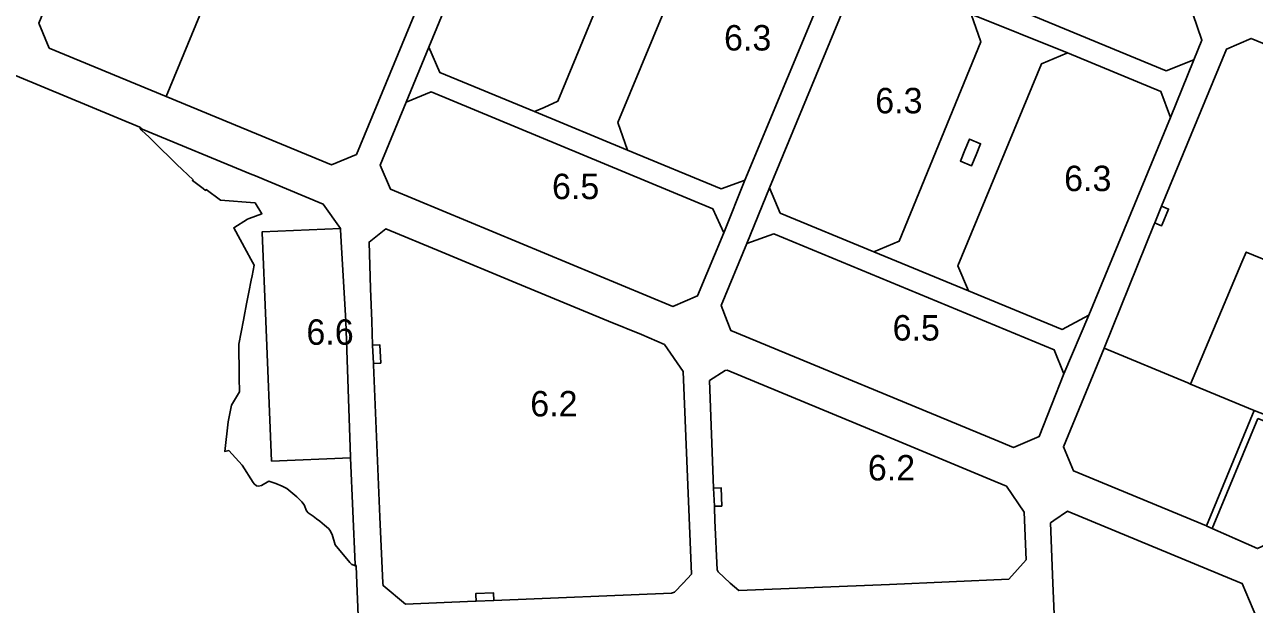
# Model space of a CAD drawing. Extents: x 598968 to 613553, y 4409678 to 4430833.
# Drawn here: x 605206 to 605786, y 4415736 to 4416009 of the extents above; entities that cross this region are included whole.
import ezdxf

# ---------------------------------------------------------------- set-up
doc = ezdxf.new("R2010")
doc.units = 0
for name, color, linetype in [('1', 7, 'Continuous'), ('Zona 6.2 - ANNEX III E', 7, 'Continuous'), ('Zona 6.3 - ANNEX III E', 7, 'Continuous'), ('Zona 6.5 - ANNEX III E', 7, 'Continuous'), ('Zona 6.6 - ANNEX III E', 7, 'Continuous')]:
    doc.layers.add(name, color=color, linetype=linetype)

msp = doc.modelspace()

# ---------------------------------------------------------------- linework, layer by layer
at = {"layer": '1'}
for points in [[(605413.2444, 4416069.7069), (605409.3441, 4416060.2821), (605400.3206, 4416038.4781), (605362.8413, 4415947.9137), (605351.0859, 4415943.0399), (605273.0979, 4415975.3137), (605273.0943, 4415975.3146), (605217.9054, 4415998.1523), (605213.031, 4416009.9096), (605290.8173, 4416197.8715), (605302.5757, 4416202.7458), (605357.7632, 4416179.9075), (605435.7532, 4416147.6329), (605440.6276, 4416135.8756)], [(605357.7632, 4416179.9075), (605302.5757, 4416202.7458), (605290.8173, 4416197.8715), (605213.031, 4416009.9096), (605217.9054, 4415998.1523), (605273.0943, 4415975.3146), (605314.0146, 4416074.194)], [(605378.8742, 4415931.583), (605374.0758, 4415942.9193), (605386.2096, 4415972.6661), (605397.0031, 4415998.6269), (605436.4772, 4416094.1213), (605447.8156, 4416121.3723), (605451.6756, 4416130.9923), (605463.8177, 4416135.792), (605596.0043, 4416080.9851), (605601.2443, 4416069.2054), (605596.8544, 4416058.5554), (605586.2696, 4416032.5788), (605546.0952, 4415935.8658), (605536.0554, 4415911.0159), (605523.7056, 4415881.2859), (605512.0544, 4415876.325)], [(605536.7596, 4416062.2366), (605492.3118, 4416080.6494), (605497.2153, 4416068.7337), (605457.836, 4415973.154), (605451.3144, 4415970.2236), (605447.6218, 4415968.5645), (605446.8861, 4415968.2339), (605490.6274, 4415950.0969), (605486.1528, 4415963.1027), (605525.295, 4416057.4442)], [(605400.3206, 4416038.4781), (605314.0146, 4416074.194), (605273.0943, 4415975.3146), (605273.0979, 4415975.3137), (605351.0859, 4415943.0399), (605362.8413, 4415947.9137)], [(605534.9055, 4415876.7261), (605546.9853, 4415906.0361), (605557.6473, 4415932.3467), (605597.0697, 4416027.6512), (605608.1698, 4416054.0843), (605612.4942, 4416064.0456), (605624.3651, 4416069.2253), (605757.3031, 4416014.3485), (605761.6531, 4416001.9487), (605757.7965, 4415992.5856), (605746.7334, 4415965.3688), (605708.314, 4415872.219), (605696.521, 4415844.501), (605684.9027, 4415814.9883), (605672.8055, 4415809.8995), (605664.0589, 4415813.5143), (605539.3425, 4415865.069), (605537.6712, 4415869.46)], [(605757.7965, 4415992.5856), (605744.8033, 4415987.4486), (605612.6443, 4416042.1758), (605608.1716, 4416054.0794), (605608.1698, 4416054.0843), (605597.0697, 4416027.6512), (605597.0744, 4416027.6532), (605609.4195, 4416032.6605), (605652.8502, 4416014.2157), (605698.1847, 4415995.9269), (605742.2155, 4415977.7057), (605746.7334, 4415965.3688)], [(605698.1847, 4415995.9269), (605652.8502, 4416014.2157), (605657.4041, 4416001.087), (605618.8546, 4415907.1673), (605606.8917, 4415902.1501), (605651.6001, 4415883.711), (605646.5345, 4415895.4679), (605685.8939, 4415990.6876), (605697.9061, 4415995.8082)], [(605446.8861, 4415968.2339), (605402.1451, 4415986.7234), (605397.0051, 4415998.6223), (605397.0031, 4415998.6269), (605386.2096, 4415972.6661), (605386.2143, 4415972.6681), (605398.1014, 4415977.5484), (605530.9554, 4415922.4057), (605536.0554, 4415911.0159), (605546.0952, 4415935.8658), (605545.711, 4415935.7281), (605543.9899, 4415935.1113), (605534.7923, 4415931.8151), (605490.6274, 4415950.0969)], [(605355.2362, 4415913.0768), (605347.158, 4415924.6423), (605314.4337, 4415938.1846), (605313.5395, 4415938.5546), (605261.6924, 4415960.0105), (605260.571, 4415960.9504), (605260.8798, 4415960.2221), (605261.2803, 4415959.6602), (605261.4944, 4415959.4646), (605265.0439, 4415956.1683), (605270.2901, 4415950.9933), (605275.0034, 4415946.3695), (605278.1279, 4415943.3045), (605285.7383, 4415936.1067), (605285.4254, 4415935.6848), (605290.4452, 4415931.9598), (605291.649, 4415931.0665), (605291.9468, 4415931.468), (605298.7404, 4415926.4624), (605314.9486, 4415925.2416), (605315.0085, 4415925.1467), (605318.2121, 4415920.0693), (605312.2428, 4415917.8544), (605311.429, 4415917.5525), (605304.9522, 4415913.4434), (605310.9899, 4415902.3558), (605313.0084, 4415898.6491), (605314.5475, 4415895.8227), (605313.5678, 4415890.7229), (605313.179, 4415888.699), (605312.0939, 4415883.0503), (605311.0275, 4415877.4992), (605309.8928, 4415871.5921), (605309.5598, 4415869.8591), (605307.3981, 4415858.6062), (605307.5178, 4415843.9522), (605307.5283, 4415842.6685), (605307.5823, 4415836.0602), (605303.854, 4415829.7247), (605302.3156, 4415821.905), (605300.7241, 4415807.9462), (605302.606, 4415808.3712), (605308.9648, 4415801.4807), (605314.0628, 4415793.2544), (605314.5213, 4415792.6602), (605315.7094, 4415791.7952), (605316.5529, 4415791.6266), (605317.9801, 4415791.9649), (605321.5554, 4415793.8687), (605324.7458, 4415792.9068), (605327.8196, 4415791.6484), (605329.9221, 4415790.4211), (605334.7373, 4415786.6255), (605337.1218, 4415784.1882), (605338.1042, 4415782.7254), (605339.3083, 4415779.9415), (605340.0639, 4415779.0656), (605342.3322, 4415777.3793), (605343.9217, 4415776.2449), (605345.5112, 4415775.1105), (605347.8213, 4415773.1917), (605348.6938, 4415772.4206), (605348.7072, 4415772.4087), (605349.6067, 4415771.6138), (605350.2642, 4415770.8176), (605351.34, 4415768.8282), (605352.7649, 4415763.9003), (605359.7785, 4415755.5556), (605359.8969, 4415755.4147), (605359.9141, 4415755.3942), (605360.4522, 4415754.754), (605360.4565, 4415754.7489), (605360.4907, 4415754.7082), (605360.8132, 4415754.5927), (605362.7145, 4415753.9115), (605362.1456, 4415754.7146), (605360.0838, 4415804.9775), (605322.8089, 4415803.448), (605322.805, 4415803.4479), (605320.0972, 4415869.4564), (605318.3859, 4415911.1749), (605318.37, 4415911.5642), (605318.3739, 4415911.5643)], [(605655.0833, 4415947.8739), (605652.9419, 4415942.6995), (605647.6752, 4415944.8791), (605649.8165, 4415950.0535), (605651.9579, 4415955.2279), (605657.2246, 4415953.0483)], [(605655.0833, 4415947.8739), (605657.2246, 4415953.0483), (605651.9579, 4415955.2279), (605649.8165, 4415950.0535), (605647.6752, 4415944.8791), (605652.9419, 4415942.6995)], [(605606.8917, 4415902.1501), (605562.7641, 4415920.3493), (605557.6494, 4415932.342), (605557.6473, 4415932.3467), (605546.9853, 4415906.0361), (605546.9899, 4415906.0378), (605559.7152, 4415910.6163), (605691.9542, 4415855.9389), (605696.521, 4415844.501), (605708.314, 4415872.219), (605695.7342, 4415865.5089), (605651.6001, 4415883.711)], [(605739.3519, 4415915.7293), (605739.3553, 4415915.7279), (605740.3602, 4415915.3083), (605742.5497, 4415914.3943), (605742.6336, 4415914.3593), (605742.8734, 4415914.9313), (605745.9335, 4415922.2293), (605742.6169, 4415923.6477), (605742.6135, 4415923.6492)], [(605512.7901, 4415741.5371), (605511.4201, 4415741.1471), (605511.4162, 4415741.147), (605427.5976, 4415737.6757), (605427.5937, 4415737.6756), (605419.2293, 4415737.3848), (605419.2254, 4415737.3846), (605418.8621, 4415737.3695), (605418.8582, 4415737.3693), (605385.8912, 4415735.9952), (605385.8874, 4415735.9951), (605375.3575, 4415744.7248), (605375.3033, 4415745.9135), (605373.8831, 4415777.0759), (605370.861, 4415848.8777), (605370.8372, 4415849.4437), (605370.4372, 4415858.0536), (605370.0115, 4415869.4573), (605369.4408, 4415884.7444), (605368.747, 4415906.7132), (605376.6082, 4415912.9627), (605403.2675, 4415901.8882), (605438.0464, 4415887.4644), (605481.6608, 4415869.4591), (605497.2059, 4415863.0416), (605508.1058, 4415858.4359), (605516.8658, 4415845.7061), (605519.1241, 4415792.0699), (605520.8761, 4415750.1371), (605516.9052, 4415745.9159), (605516.9092, 4415745.9159)], [(605869.8234, 4415865.9385), (605868.8373, 4415866.3466), (605861.4561, 4415869.4012), (605859.6588, 4415865.0584), (605854.0224, 4415867.3909), (605855.8197, 4415871.7337), (605811.673, 4415890.003), (605782.5432, 4415901.9801), (605780.5183, 4415897.185), (605756.2662, 4415839.756), (605786.3011, 4415827.3268), (605819.1595, 4415814.5422), (605820.1695, 4415816.4572), (605824.1395, 4415814.4072), (605828.9013, 4415823.0512), (605834.283, 4415831.3233), (605840.256, 4415839.1794), (605846.7878, 4415846.5772), (605853.8437, 4415853.4769), (605861.3857, 4415859.8417), (605869.3734, 4415865.6373)], [(605370.8372, 4415849.4437), (605370.8411, 4415849.4439), (605373.8877, 4415849.5953), (605374.2571, 4415849.6137), (605373.8671, 4415858.1636), (605370.4411, 4415858.0537), (605370.4372, 4415858.0536)], [(605756.2662, 4415839.756), (605756.2637, 4415839.7502), (605754.9408, 4415840.3044), (605715.5019, 4415856.6255), (605715.4985, 4415856.6269), (605696.2671, 4415810.1565), (605700.9829, 4415798.7817), (605763.7403, 4415772.8115), (605786.3011, 4415827.3268)], [(605611.3067, 4415815.8497), (605664.0589, 4415793.8101), (605669.3747, 4415791.5892), (605677.8546, 4415779.3595), (605678.7147, 4415756.7797), (605670.4848, 4415747.6996), (605614.2069, 4415745.2727), (605614.2029, 4415745.2725), (605543.1798, 4415742.3277), (605543.1759, 4415742.3276), (605539.1829, 4415745.9162), (605533.3959, 4415751.1173), (605532.9359, 4415752.1873), (605531.9457, 4415775.3474), (605531.6804, 4415781.5541), (605531.6559, 4415782.127), (605531.2958, 4415790.6369), (605529.3757, 4415841.3564), (605536.8156, 4415846.1364), (605537.7461, 4415846.2163)], [(605531.6559, 4415782.127), (605531.6598, 4415782.1271), (605534.84, 4415782.2257), (605535.1398, 4415782.2351), (605534.8758, 4415790.757), (605531.2998, 4415790.6371), (605531.2958, 4415790.6369)], [(605427.5937, 4415737.6756), (605427.4466, 4415741.2935), (605419.0808, 4415740.9457), (605419.1039, 4415740.3762), (605419.2254, 4415737.3846), (605419.2293, 4415737.3848)]]:
    msp.add_lwpolyline(points, close=True, dxfattribs=at)
for points in [[(605787.7946, 4415762.1719), (605764.015, 4415772.69), (605763.7403, 4415772.8115), (605700.9829, 4415798.7817), (605696.2671, 4415810.1565), (605715.4985, 4415856.6269), (605739.0872, 4415915.0891), (605739.3519, 4415915.7293), (605742.6135, 4415923.6492), (605773.273, 4415997.7389), (605784.8836, 4416002.7326), (605942.2816, 4415937.7923)], [(605191.6574, 4415989.4688), (605260.571, 4415960.9504), (605261.6924, 4415960.0105), (605313.5395, 4415938.5546), (605314.4337, 4415938.1846), (605347.158, 4415924.6423), (605355.2362, 4415913.0768), (605355.2617, 4415912.6443), (605355.6034, 4415906.8447), (605357.8064, 4415869.4571), (605360.0687, 4415805.4066), (605360.0838, 4415804.9775), (605362.1456, 4415754.7146), (605362.7145, 4415753.9115), (605363.0426, 4415745.9133), (605363.9854, 4415722.9302)], [(605363.9854, 4415722.9302), (605363.0426, 4415745.9133), (605362.7145, 4415753.9115), (605360.8132, 4415754.5927), (605360.4907, 4415754.7082), (605360.4565, 4415754.7489), (605360.4522, 4415754.754), (605359.9141, 4415755.3942), (605359.8969, 4415755.4147), (605359.7785, 4415755.5556), (605352.7649, 4415763.9003), (605351.34, 4415768.8282), (605350.2642, 4415770.8176), (605349.6067, 4415771.6138), (605348.7072, 4415772.4087), (605348.6938, 4415772.4206), (605347.8213, 4415773.1917), (605345.5112, 4415775.1105), (605343.9217, 4415776.2449), (605342.3322, 4415777.3793), (605340.0639, 4415779.0656), (605339.3083, 4415779.9415), (605338.1042, 4415782.7254), (605337.1218, 4415784.1882), (605334.7373, 4415786.6255), (605329.9221, 4415790.4211), (605327.8196, 4415791.6484), (605324.7458, 4415792.9068), (605321.5554, 4415793.8687), (605317.9801, 4415791.9649), (605316.5529, 4415791.6266), (605315.7094, 4415791.7952), (605314.5213, 4415792.6602), (605314.0628, 4415793.2544), (605308.9648, 4415801.4807), (605302.606, 4415808.3712), (605300.7241, 4415807.9462), (605302.3156, 4415821.905), (605303.854, 4415829.7247), (605307.5823, 4415836.0602), (605307.5283, 4415842.6685), (605307.5178, 4415843.9522), (605307.3981, 4415858.6062), (605309.5598, 4415869.8591), (605309.8928, 4415871.5921), (605311.0275, 4415877.4992), (605312.0939, 4415883.0503), (605313.179, 4415888.699), (605313.5678, 4415890.7229), (605314.5475, 4415895.8227), (605313.0084, 4415898.6491), (605310.9899, 4415902.3558), (605304.9522, 4415913.4434), (605311.429, 4415917.5525), (605312.2428, 4415917.8544), (605318.2121, 4415920.0693), (605315.0085, 4415925.1467), (605314.9486, 4415925.2416), (605298.7404, 4415926.4624), (605291.9468, 4415931.468), (605291.649, 4415931.0665), (605290.4452, 4415931.9598), (605285.4254, 4415935.6848), (605285.7383, 4415936.1067), (605278.1279, 4415943.3045), (605275.0034, 4415946.3695), (605270.2901, 4415950.9933), (605265.0439, 4415956.1683), (605261.4944, 4415959.4646), (605261.2803, 4415959.6602), (605260.8798, 4415960.2221), (605260.571, 4415960.9504), (605191.6574, 4415989.4688)], [(605692.1742, 4415724.0429), (605691.3339, 4415745.9188), (605690.2445, 4415774.2797), (605691.806, 4415775.3501), (605698.2256, 4415779.7493), (605698.5244, 4415779.6198), (605780.1283, 4415745.9203), (605780.6338, 4415745.7115), (605789.3038, 4415725.3319)]]:
    msp.add_lwpolyline(points, dxfattribs=at)
at = {"layer": 'Zona 6.2 - ANNEX III E'}
for points in [[(605427.5937, 4415737.6756), (605427.5976, 4415737.6757), (605511.4162, 4415741.147), (605511.4201, 4415741.1471), (605512.7901, 4415741.5371), (605516.9092, 4415745.9159), (605516.9052, 4415745.9159), (605520.8761, 4415750.1371), (605519.1241, 4415792.0699), (605516.8658, 4415845.7061), (605508.1058, 4415858.4359), (605497.2059, 4415863.0416), (605481.6608, 4415869.4591), (605438.0464, 4415887.4644), (605403.2675, 4415901.8882), (605376.6082, 4415912.9627), (605368.747, 4415906.7132), (605369.4408, 4415884.7444), (605370.0115, 4415869.4573), (605370.4372, 4415858.0536), (605370.4411, 4415858.0537), (605373.8671, 4415858.1636), (605374.2571, 4415849.6137), (605373.8877, 4415849.5953), (605370.8411, 4415849.4439), (605370.8372, 4415849.4437), (605370.861, 4415848.8777), (605373.8831, 4415777.0759), (605375.3033, 4415745.9135), (605375.3575, 4415744.7248), (605385.8874, 4415735.9951), (605385.8912, 4415735.9952), (605418.8582, 4415737.3693), (605418.8621, 4415737.3695), (605419.2254, 4415737.3846), (605419.1039, 4415740.3762), (605419.0808, 4415740.9457), (605427.4466, 4415741.2935)], [(605531.6559, 4415782.127), (605531.6804, 4415781.5541), (605531.9457, 4415775.3474), (605532.9359, 4415752.1873), (605533.3959, 4415751.1173), (605539.1829, 4415745.9162), (605543.1759, 4415742.3276), (605543.1798, 4415742.3277), (605614.2029, 4415745.2725), (605614.2069, 4415745.2727), (605670.4848, 4415747.6996), (605678.7147, 4415756.7797), (605677.8546, 4415779.3595), (605669.3747, 4415791.5892), (605664.0589, 4415793.8101), (605611.3067, 4415815.8497), (605537.7461, 4415846.2163), (605536.8156, 4415846.1364), (605529.3757, 4415841.3564), (605531.2958, 4415790.6369), (605531.2998, 4415790.6371), (605534.8758, 4415790.757), (605535.1398, 4415782.2351), (605534.84, 4415782.2257), (605531.6598, 4415782.1271)]]:
    msp.add_lwpolyline(points, close=True, dxfattribs=at)
msp.add_lwpolyline([(605789.3038, 4415725.3319), (605780.6338, 4415745.7115), (605780.1283, 4415745.9203), (605698.5244, 4415779.6198), (605698.2256, 4415779.7493), (605691.806, 4415775.3501), (605690.2445, 4415774.2797), (605691.3339, 4415745.9188), (605692.1742, 4415724.0429)], dxfattribs=at)
at = {"layer": 'Zona 6.3 - ANNEX III E'}
for points in [[(605492.3118, 4416080.6494), (605448.2057, 4416098.9026), (605436.482, 4416094.1233), (605436.4772, 4416094.1213), (605397.0031, 4415998.6269), (605397.0051, 4415998.6223), (605402.1451, 4415986.7234), (605446.8861, 4415968.2339), (605447.6218, 4415968.5645), (605451.3144, 4415970.2236), (605457.836, 4415973.154), (605497.2153, 4416068.7337)], [(605586.2696, 4416032.5788), (605581.5221, 4416043.7957), (605536.7596, 4416062.2366), (605525.295, 4416057.4442), (605486.1528, 4415963.1027), (605490.6274, 4415950.0969), (605534.7923, 4415931.8151), (605543.9899, 4415935.1113), (605545.711, 4415935.7281), (605546.0952, 4415935.8658)], [(605652.8502, 4416014.2157), (605609.4195, 4416032.6605), (605597.0744, 4416027.6532), (605597.0697, 4416027.6512), (605557.6473, 4415932.3467), (605557.6494, 4415932.342), (605562.7641, 4415920.3493), (605606.8917, 4415902.1501), (605618.8546, 4415907.1673), (605657.4041, 4416001.087)], [(605746.7334, 4415965.3688), (605742.2155, 4415977.7057), (605698.1847, 4415995.9269), (605697.9061, 4415995.8082), (605685.8939, 4415990.6876), (605646.5345, 4415895.4679), (605651.6001, 4415883.711), (605695.7342, 4415865.5089), (605708.314, 4415872.219)], [(605787.9814, 4415823.5417), (605766.5123, 4415771.6643), (605787.7946, 4415762.1719), (605806.3234, 4415770.8317), (605822.4485, 4415809.999)]]:
    msp.add_lwpolyline(points, close=True, dxfattribs=at)
msp.add_lwpolyline([(605942.2816, 4415937.7923), (605784.8836, 4416002.7326), (605773.273, 4415997.7389), (605742.6135, 4415923.6492), (605742.6169, 4415923.6477), (605745.9335, 4415922.2293), (605742.8734, 4415914.9313), (605742.6336, 4415914.3593), (605742.5497, 4415914.3943), (605740.3602, 4415915.3083), (605739.3553, 4415915.7279), (605739.3519, 4415915.7293), (605739.0872, 4415915.0891), (605715.4985, 4415856.6269), (605715.5019, 4415856.6255), (605754.9408, 4415840.3044), (605756.2637, 4415839.7502), (605756.2662, 4415839.756), (605780.5183, 4415897.185), (605782.5432, 4415901.9801), (605811.673, 4415890.003)], dxfattribs=at)
at = {"layer": 'Zona 6.5 - ANNEX III E'}
for points in [[(605757.7965, 4415992.5856), (605761.6531, 4416001.9487), (605757.3031, 4416014.3485), (605624.3651, 4416069.2253), (605612.4942, 4416064.0456), (605608.1698, 4416054.0843), (605608.1716, 4416054.0794), (605612.6443, 4416042.1758), (605744.8033, 4415987.4486)], [(605536.0554, 4415911.0159), (605530.9554, 4415922.4057), (605398.1014, 4415977.5484), (605386.2143, 4415972.6681), (605386.2096, 4415972.6661), (605374.0758, 4415942.9193), (605378.8742, 4415931.583), (605512.0544, 4415876.325), (605523.7056, 4415881.2859)], [(605696.521, 4415844.501), (605691.9542, 4415855.9389), (605559.7152, 4415910.6163), (605546.9899, 4415906.0378), (605546.9853, 4415906.0361), (605534.9055, 4415876.7261), (605537.6712, 4415869.46), (605539.3425, 4415865.069), (605664.0589, 4415813.5143), (605672.8055, 4415809.8995), (605684.9027, 4415814.9883)]]:
    msp.add_lwpolyline(points, close=True, dxfattribs=at)
at = {"layer": 'Zona 6.6 - ANNEX III E'}
msp.add_lwpolyline([(605360.0838, 4415804.9775), (605360.0687, 4415805.4066), (605357.8064, 4415869.4571), (605355.6034, 4415906.8447), (605355.2617, 4415912.6443), (605355.2362, 4415913.0768), (605318.3739, 4415911.5643), (605318.37, 4415911.5642), (605318.3859, 4415911.1749), (605320.0972, 4415869.4564), (605322.805, 4415803.4479), (605322.8089, 4415803.448)], close=True, dxfattribs=at)

# ---------------------------------------------------------------- texts
at = {"layer": 'Zona 6.2 - ANNEX III E'}
for p in [(605444.8116, 4415824.4789), (605604.0452, 4415794.2719)]:
    msp.add_text('6.2', height=12, dxfattribs=at).set_placement(p)
at = {"layer": 'Zona 6.3 - ANNEX III E'}
for p in [(605536.2112, 4415997.0258), (605607.5257, 4415967.4053), (605696.634, 4415930.7179)]:
    msp.add_text('6.3', height=12, dxfattribs=at).set_placement(p)
at = {"layer": 'Zona 6.5 - ANNEX III E'}
for p in [(605455.0656, 4415926.9367), (605615.7133, 4415860.2579)]:
    msp.add_text('6.5', height=12, dxfattribs=at).set_placement(p)
at = {"layer": 'Zona 6.6 - ANNEX III E'}
msp.add_text('6.6', height=12, dxfattribs=at).set_placement((605339.2269, 4415858.2623))

doc.saveas('drawing.dxf')
